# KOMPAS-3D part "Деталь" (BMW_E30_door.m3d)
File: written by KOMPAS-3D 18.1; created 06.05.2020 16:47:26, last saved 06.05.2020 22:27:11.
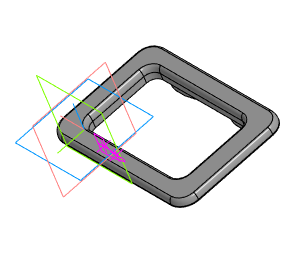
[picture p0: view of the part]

Document properties: Автор: Grisha; Полное имя файла: C:\Users\Grisha\Desktop\3d\BMW E30 door.m3d

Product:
- Part/product: Деталь
    Масса: 0.117329

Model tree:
1. Эскиз:1
2. Элемент выдавливания:1
     Расстояние 1 = 4.5
3. Эскиз:2
4. Элемент выдавливания:2
     Расстояние 2 = -2.5
5. Скругление:1  (with: Элемент выдавливания:2)
     Радиус = 1.5
6. Скругление:2  (with: Элемент выдавливания:1)
     Полуось 1 = 4; Полуось 2 = 2
7. Эскиз:4
8. Элемент выдавливания:3
     Расстояние 1 = 4; Расстояние 2 = 2.5
9. Скругление:3  (with: Элемент выдавливания:1)
     Полуось 1 = 4; Полуось 2 = 2
10. Скругление:4  (with: Элемент выдавливания:3)
     Полуось 1 = 1
11. Эскиз:5
12. Крепление
     Толщина стенки 2 = 4; Расстояние 1 = 2; Расстояние 2 = -4
13. Массив вдоль кривой:3
14. Экземпляр ( 1 )
15. Экземпляр ( 2 )  (with: Крепление, Элемент выдавливания:3)
     Шаг = 46
16. Скругление:5
     Радиус = 3
17. Скругление:6
     Радиус = 3
18. Массив по сетке:2  (with: Массив вдоль кривой:3, Крепление, Элемент выдавливания:3)  (4 pattern instances)
     Шаг 1 = 53; Угол раствора = 90
19. Скругление:7
     Радиус = 3
20. Скругление:8
     Радиус = 3
21. Эскиз:6  (with: Скругление:4)
22. Элемент выдавливания:5
     Расстояние 1 = 22; Расстояние 2 = -21
23. Скругление:9  (with: Элемент выдавливания:5)
     Полуось 1 = 11; Полуось 2 = 6
24. Скругление:10  (with: Элемент выдавливания:5)
     Радиус = 1; Полуось 2 = 6; Коэффициент = 0.39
